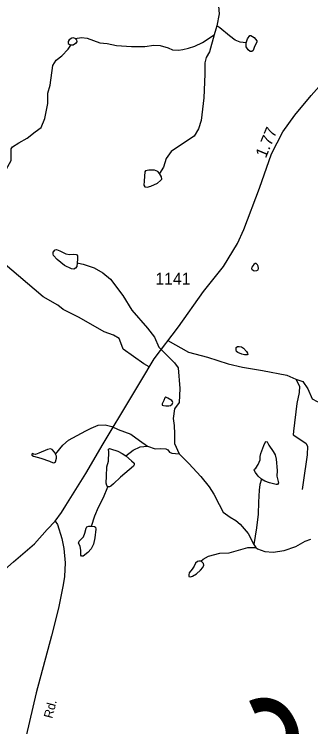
# Model space of a CAD drawing. Extents: x 2056842 to 2160602, y 826753 to 1016856.
# Drawn here: x 2064087 to 2067225, y 918502 to 926037 of the extents above; entities that cross this region are included whole.
import ezdxf

# ---------------------------------------------------------------- set-up
doc = ezdxf.new("R2010")
doc.units = 0
for name, color, linetype in [('Exist Hydrographic Creek Single Shore', 7, 'Continuous'), ('Exist Hydrographic Misc Water Feature', 7, 'Continuous'), ('Exist Road Non-System Type 51', 7, 'Continuous'), ('Exist Road Secondary Mileage Hundredths English Label', 7, 'Continuous'), ('Exist Road Secondary Structure Standard Bridge Number Label', 7, 'Continuous'), ('Exist Road Secondary Type 41 Attributed', 7, 'Continuous'), ('Exist Road Secondary Type 51 Attributed', 7, 'Continuous'), ('Exist Road Secondary Type 51 Label', 7, 'Continuous'), ('Exist Road Secondary Type 51 Number Label', 7, 'Continuous')]:
    doc.layers.add(name, color=color, linetype=linetype)

msp = doc.modelspace()

# ---------------------------------------------------------------- linework, layer by layer
at = {"layer": 'Exist Hydrographic Creek Single Shore'}
for points in [[(2066227, 927273.8), (2066283.1, 927129.9), (2066337.5, 926905.9), (2066341.9, 926801.8), (2066334, 926733.7), (2066298.2, 926625.9), (2066314.4, 926453.9), (2066252.8, 926253.7), (2066245.1, 926165.6), (2066257.3, 926041.6), (2066231.6, 925913.9)], [(2064731.1, 925779), (2064800, 925791.2), (2064859.9, 925783.3), (2064994, 925735.5), (2065072.1, 925727.7), (2065168.1, 925707.9), (2065328.1, 925696.1), (2065468.1, 925696.5), (2065564.1, 925708.7), (2065632.7, 925707.3), (2065714.6, 925681.7), (2065761.9, 925658.7), (2065825.9, 925657.4), (2065870.7, 925663.8), (2065930.1, 925679.2), (2065996.7, 925700.9), (2066078.5, 925739.3), (2066202.6, 925820)], [(2066202.6, 925820), (2066154.1, 925639.5), (2066120, 925579.5), (2066104.1, 925521.4), (2066103.9, 925402), (2066093.6, 925153.7), (2066066.8, 924914.3), (2066036.1, 924826), (2065991.3, 924747.9), (2065941.4, 924717.2), (2065746.1, 924586.7), (2065694.5, 924511.1), (2065667.6, 924420.2), (2065625.4, 924351.1)], [(2064752.1, 923407.3), (2064768.5, 923405.3), (2064816.4, 923393.3), (2064932.5, 923353.5), (2065024.6, 923301.7), (2065104.8, 923233.9), (2065237, 923064.1), (2065331.3, 922908.4), (2065497.6, 922716.6), (2065571.9, 922620.8), (2065617, 922515.5), (2065782.2, 922351.2), (2065820.4, 922299.2), (2065838.3, 922077.7), (2065831.9, 921930.5), (2065782, 921863.9), (2065770.5, 921760.3), (2065778.2, 921687.3), (2065782, 921600.3), (2065784.6, 921497.8), (2065834.2, 921389)], [(2065834.2, 921389), (2065934, 921285.4), (2066062.6, 921147.8), (2066148.7, 921039.9), (2066200.1, 920961.5), (2066255.1, 920852.1), (2066296.8, 920770.1), (2066372.3, 920717.7), (2066433.7, 920681.8), (2066477.2, 920643.4), (2066561.6, 920547.4), (2066624.3, 920429.6)], [(2066643.9, 920398.8), (2066660.1, 920382.9), (2066740, 920355.1), (2066828, 920349.2), (2066944.1, 920365.4), (2067065.9, 920409.7), (2067167.8, 920465.9), (2067225.8, 920486)]]:
    msp.add_lwpolyline(points, dxfattribs=at)
at = {"layer": 'Exist Hydrographic Misc Water Feature'}
msp.add_line((2066624.3, 920429.6), (2066643.9, 920398.8), dxfattribs=at)
for points in [[(2066231.6, 925913.9), (2066221.8, 925878.9), (2066202.6, 925820)], [(2066541.6, 925732.9), (2066477.7, 925740.6), (2066426.5, 925761.1), (2066366.4, 925809.7), (2066263.7, 925893.9), (2066231.7, 925913.9)], [(2064731.1, 925779), (2064711.9, 925786.7), (2064696.5, 925785.4), (2064667.1, 925767.5), (2064656.9, 925747), (2064658.2, 925726.5), (2064668.4, 925718.9), (2064685, 925711.2)], [(2064731.1, 925779), (2064745.2, 925766.2), (2064747.7, 925744.5), (2064734.9, 925726.5), (2064710.6, 925711.2), (2064685, 925711.2)], [(2066541.6, 925732.9), (2066554.4, 925775.2), (2066580, 925811), (2066591.5, 925811), (2066624.8, 925791.8), (2066654.2, 925757.3), (2066652.9, 925741.9), (2066631.2, 925694.5), (2066617.1, 925652.3), (2066601.8, 925643.3), (2066582.6, 925643.3), (2066562.1, 925658.7), (2066541.6, 925692), (2066541.6, 925732.9)], [(2063911.2, 924215.4), (2063952.1, 924299.9), (2063985.4, 924362.6), (2064053.2, 924490.7), (2064054.5, 924614.8), (2064069.7, 924633.4), (2064136.2, 924675.6), (2064223.2, 924725.5), (2064310.2, 924794.7), (2064371.6, 924840.7), (2064410, 924934.2), (2064442, 925092.9), (2064443.2, 925201.7), (2064466.3, 925286.2), (2064497, 925496.1), (2064531.5, 925551.2), (2064589.1, 925598.5), (2064656.9, 925667.7), (2064685, 925711.2)], [(2065625.4, 924351.1), (2065605.1, 924373.5), (2065573.1, 924387.6), (2065511.7, 924387.6), (2065475.9, 924382.5), (2065469.5, 924371), (2065466.9, 924326.2), (2065461.8, 924271.1), (2065458, 924228.9), (2065469.5, 924212.2), (2065492.5, 924208.4), (2065530.9, 924218.6), (2065602.5, 924249.4), (2065635.8, 924277.5), (2065647.3, 924294.2), (2065644.7, 924317.2), (2065625.4, 924351.1)], [(2064752.1, 923407.3), (2064748.4, 923369.3), (2064735.6, 923350.1), (2064718.9, 923341.1), (2064694.6, 923345), (2064620.4, 923380.8), (2064542.4, 923443.5), (2064504, 923484.5), (2064497.6, 923499.8), (2064500.2, 923519), (2064521.9, 923545.9), (2064533.4, 923547.2), (2064570.5, 923535.7), (2064634.5, 923503.7), (2064670.3, 923497.3), (2064717.7, 923501.1), (2064744.5, 923496), (2064756, 923480.6), (2064757.3, 923447.4), (2064752.1, 923407.3)], [(2066660.1, 923387.3), (2066646.3, 923400.1), (2066636.8, 923400.1), (2066623.5, 923390.6), (2066600.7, 923362.3), (2066599.1, 923349.5), (2066603, 923341.2), (2066617.9, 923326.7), (2066634, 923323.4), (2066653.5, 923326.2), (2066667.4, 923335.1), (2066670.7, 923349.5), (2066669, 923371.2), (2066660.1, 923387.3)], [(2066512.2, 922503.9), (2066545.8, 922469.6), (2066557.4, 922451.9), (2066558, 922440.3), (2066551.3, 922436.6), (2066525.6, 922436.6), (2066495.1, 922442.1), (2066452.3, 922458.6), (2066437.7, 922470.3), (2066434.6, 922484.9), (2066437.1, 922513.6), (2066449.3, 922524), (2066468.8, 922524.7), (2066492, 922517.9), (2066512.2, 922503.9)], [(2065669.4, 921953.5), (2065658.9, 921929.6), (2065651.3, 921915.6), (2065654.2, 921904.5), (2065665.3, 921898.7), (2065692.1, 921894.6), (2065722.4, 921895.8), (2065739.3, 921901), (2065756.8, 921915), (2065763.8, 921930.2), (2065762.7, 921941.9), (2065753.9, 921951.2), (2065711.9, 921975.1), (2065692.1, 921988.5), (2065686.9, 921988.5), (2065679.3, 921979.8), (2065669.4, 921953.5)], [(2064524.4, 921385.2), (2064602, 921481), (2064662, 921533.1), (2064844, 921629.7), (2064900.3, 921657.9), (2064973.5, 921689.6), (2065049.6, 921693.8), (2065121.6, 921677.9), (2065185.7, 921646.1), (2065321.7, 921594.4), (2065413.8, 921528.5), (2065498, 921470.6)], [(2066702.3, 921119), (2066669.1, 921152.9), (2066639.6, 921190), (2066626.8, 921216.9), (2066629.4, 921227.1), (2066642.2, 921237.4), (2066670.3, 921274.5), (2066690.8, 921324.4), (2066690.8, 921361.5), (2066697.2, 921392.2), (2066729.2, 921478), (2066745.8, 921516.4), (2066753.5, 921520.2), (2066763.7, 921515.1), (2066782.9, 921480.6), (2066829, 921414), (2066848.2, 921376.9), (2066858.4, 921330.8), (2066868.6, 921211.8), (2066867.3, 921152.9), (2066884, 921079.9), (2066873.7, 921064.5), (2066858.4, 921063.3), (2066788, 921081.2), (2066738.1, 921099.1), (2066702.3, 921119)], [(2064524.4, 921385.2), (2064514.1, 921404.4), (2064487.3, 921435.1), (2064469.4, 921441.5), (2064439.9, 921433.8), (2064346.5, 921396.7), (2064313.3, 921382.6), (2064291.5, 921383.9), (2064280, 921391.6), (2064273.6, 921383.9), (2064274.9, 921373.7), (2064291.5, 921363.4), (2064369.6, 921341.7), (2064459.1, 921309.7), (2064497.5, 921294.3), (2064512.8, 921295.6), (2064523.1, 921302), (2064534.6, 921341.7), (2064533.3, 921364.7), (2064524.4, 921385.2)], [(2065077, 921040.9), (2065065.5, 921054.3), (2065059.1, 921078.6), (2065062.9, 921150.3), (2065065.5, 921251.4), (2065084.7, 921310.3), (2065088.5, 921406.3), (2065086, 921438.3), (2065094.9, 921443.4), (2065106.4, 921439.6), (2065183.2, 921417.8), (2065230.5, 921392.2), (2065268.9, 921366.6)], [(2065268.9, 921366.6), (2065346.9, 921425.5), (2065418.1, 921460.6), (2065498, 921470.6)], [(2065498, 921470.6), (2065578.6, 921440.2), (2065636.2, 921445.4), (2065689.9, 921440.2), (2065711.7, 921430), (2065729.6, 921405.7), (2065755.1, 921394.2), (2065834.2, 921389)], [(2065268.9, 921366.6), (2065327.7, 921315.4), (2065354.6, 921288.6), (2065357.2, 921273.2), (2065349.5, 921259.1), (2065302.2, 921220.7), (2065211.3, 921142.6), (2065135.9, 921069.7), (2065107.7, 921045.3), (2065093.6, 921038.9), (2065077, 921040.9)], [(2066702.3, 921119), (2066687, 921062.6), (2066678, 921002.5), (2066671.6, 920875.7), (2066667.8, 920750.9), (2066651.1, 920606.3), (2066624.3, 920429.6)], [(2064905.6, 920623.6), (2064938.8, 920732.4), (2064979.8, 920824.5), (2065031, 920926.9), (2065077, 921040.9)], [(2064905.6, 920623.6), (2064937.6, 920621), (2064947.8, 920613.3), (2064951.6, 920592.9), (2064941.4, 920500.7), (2064924.8, 920431.6), (2064900.5, 920382.9), (2064867.2, 920345.8), (2064816, 920306.1), (2064799.4, 920307.4), (2064793, 920317.6), (2064793, 920367.6), (2064785.3, 920411.1), (2064767.4, 920441.8), (2064772.5, 920463.6), (2064789.2, 920477.6), (2064819.9, 920510.9), (2064833.9, 920550.6), (2064848, 920601.8), (2064855.7, 920617.2), (2064874.9, 920622.3), (2064905.6, 920623.6)], [(2066060.8, 920254.2), (2066085.7, 920276), (2066144.2, 920305.9), (2066264.1, 920336.2), (2066360.1, 920342.3), (2066560, 920398.7), (2066643.9, 920398.8)], [(2066060.8, 920254.2), (2066042.2, 920253), (2066028.1, 920247.9), (2066006.4, 920231.2), (2065989.8, 920201.8), (2065970.6, 920167.2), (2065939.9, 920131.4), (2065933.5, 920107.1), (2065936, 920091.7), (2065951.4, 920087.9), (2065974.4, 920094.3), (2066016.6, 920119.9), (2066058.8, 920159.6), (2066084.4, 920187.7), (2066094.7, 920212), (2066088.3, 920230), (2066072.9, 920246.6), (2066060.8, 920254.2)]]:
    msp.add_lwpolyline(points, dxfattribs=at)
at = {"layer": 'Exist Road Non-System Type 51'}
for points in [[(2065515.8, 922306.6), (2065458.4, 922341.6), (2065241, 922496.2), (2065214.1, 922560.9), (2065197.9, 922607.7), (2065136.9, 922641.8), (2065039.9, 922677.8), (2064774.9, 922831.5), (2064604.2, 922915.9), (2064546.8, 922960.9), (2064392.3, 923047.2), (2063965.7, 923411.2), (2063924.3, 923510), (2063809.4, 923641.3), (2063560.6, 923897.4), (2063397.1, 924050.2), (2063346.8, 924082.6), (2063158.2, 924149.1), (2063105.2, 924187.7), (2063072.9, 924232.7)], [(2065713.9, 922585.1), (2065931.7, 922463), (2066131.1, 922410.8), (2066350.3, 922338.9), (2066502.9, 922304.8), (2066714.9, 922268.8), (2066970.9, 922221.2), (2067066.1, 922176.2)], [(2067066.1, 922176.2), (2067107.4, 922104.3), (2067102, 922036), (2067078.7, 921919.2), (2067042.7, 921626.2), (2067040, 921589.3), (2067173, 921501.3), (2067189.1, 921470.7), (2067185.5, 921379), (2067144.2, 921086), (2067134.3, 921009.6)], [(2067066.1, 922176.2), (2067139.7, 922152.9), (2067193.6, 922073.8), (2067240.3, 921971.3), (2067292.4, 921940.8), (2067360.7, 921937.2), (2067479.2, 921935.4), (2067619.4, 921953.4), (2067678.6, 921974.9)]]:
    msp.add_lwpolyline(points, dxfattribs=at)
at = {"layer": 'Exist Road Secondary Type 41 Attributed'}
msp.add_lwpolyline([(2064520.1, 920676.8), (2064546.1, 920639.1), (2064589.2, 920491.8), (2064610.7, 920385.7), (2064625.1, 920236.6), (2064617.9, 920091.1), (2064606.2, 920002.1), (2064556, 919757.7), (2064479.7, 919463.9), (2064319.8, 918862), (2064141.2, 918104.6)], dxfattribs=at)
at = {"layer": 'Exist Road Secondary Type 51 Attributed'}
for points in [[(2064520.1, 920676.8), (2064586.5, 920767.6), (2064631.8, 920840.8), (2064844.6, 921179.5), (2065029.6, 921494), (2065319.6, 921981.8), (2065425.5, 922157.9), (2065567.3, 922391.5), (2065825, 922732), (2066090.8, 923105.7), (2066300, 923370.8), (2066449, 923611.6), (2066517.2, 923760.7), (2066681.5, 924198.2), (2066809, 924559.4), (2066929.3, 924794.8), (2067057.7, 924970), (2067230.1, 925176.6), (2067503, 925489.3), (2067688.9, 925680.6), (2068091.1, 926092.1)], [(2059705.6, 918674.5), (2059839.8, 918687.7), (2060257.3, 918762.3), (2061272.7, 918942.9), (2061540.2, 919002.2), (2061890.4, 919095.6), (2062300.7, 919238.4), (2062857.3, 919455.9), (2063121.3, 919569.1), (2063377.1, 919713.7), (2063580, 919837.7), (2063836.8, 920035.4), (2064079.2, 920245.6), (2064301.4, 920437.4), (2064435.2, 920586.5), (2064520.1, 920676.8)]]:
    msp.add_lwpolyline(points, dxfattribs=at)

# ---------------------------------------------------------------- texts
at = {"layer": 'Exist Road Secondary Mileage Hundredths English Label'}
msp.add_text('1.77', height=125, rotation=67.42229, dxfattribs=at).set_placement((2066749.9, 924508.4))
at = {"layer": 'Exist Road Secondary Structure Standard Bridge Number Label'}
msp.add_text('225', height=1230.31, rotation=300, dxfattribs=at).set_placement((2065725.9, 918389.3))
at = {"layer": 'Exist Road Secondary Type 51 Label'}
msp.add_text('Rd.', height=95, rotation=75.55238, dxfattribs=at).set_placement((2064489.4, 918583.6))
at = {"layer": 'Exist Road Secondary Type 51 Number Label'}
msp.add_text('1141', height=125, dxfattribs=at).set_placement((2065580.4, 923177.7))

doc.saveas('drawing.dxf')
